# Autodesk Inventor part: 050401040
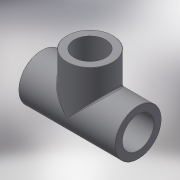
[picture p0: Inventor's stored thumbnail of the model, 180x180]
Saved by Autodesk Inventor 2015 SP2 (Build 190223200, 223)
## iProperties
Created: 2017-10
Part Number: 050401040
Material: Generic
Description: PLASSON THREADED TEE PVC 4"
Document SubType Name: Modeling
Designer: KIM
Density: 1 g/cm^3
Appearance: Default
Author: KIM
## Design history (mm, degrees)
derived "050401.ipt"
feature "Solid1::050401.ipt"
feature "Solid2::050401.ipt"
tag "TaggingFeature1"
body "Solid1"
other parameters: "d0" = 239, "d1" = 132, "d4" = 110.072, "d5" = 99.0648, "d7" = 1.10072, "d9" = 119.5, "d10" = 132, "d15" = 0, "d18" = 110.072, "d24" = 1.10072, "d30" = 110.072, "d32" = 0, "d33" = 99.0648, "d35" = 0, "d36" = 5.5036, "G_" = 110.072, "E_" = 132, "H_" = 239
